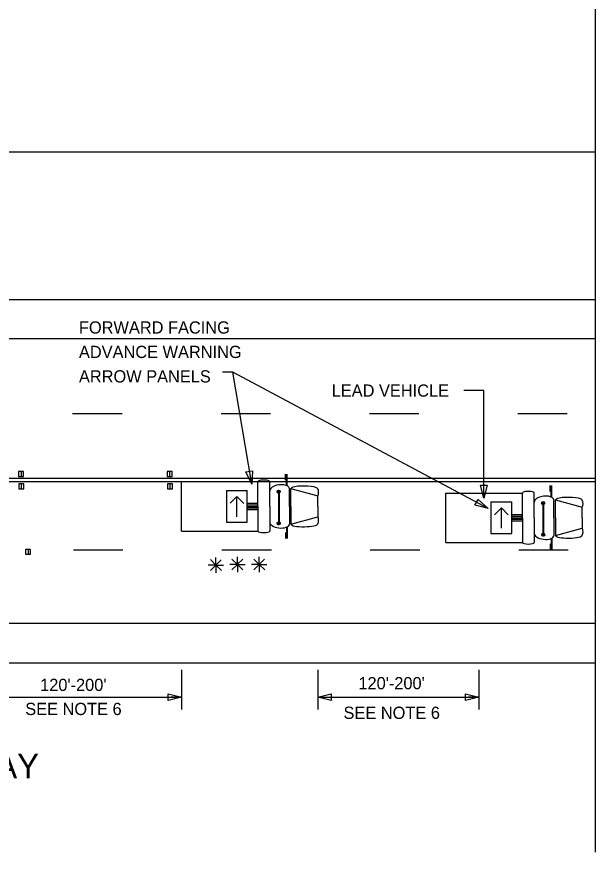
# Model space of a CAD drawing. Extents: x -747 to 834, y -5485 to -3577.
# Drawn here: x -230.7 to 53, y -5484.5 to -5074.5 of the extents above; entities that cross this region are included whole.
import ezdxf

# ---------------------------------------------------------------- set-up
doc = ezdxf.new("R2010")
doc.units = 0
doc.layers.add('Working Level 1', color=7, linetype='Continuous')

msp = doc.modelspace()

# ---------------------------------------------------------------- linework, layer by layer
at = {"layer": 'Working Level 1'}
for p, q in [((52.99, -4442.19), (52.99, -5484.51)), ((-746.8, -5140.74), (52.65, -5140.74)), ((-470.08, -5213.17), (52.99, -5213.17)), ((-475.5, -5232.41), (52.99, -5232.41)), ((0.51, -5315.84), (-124.65, -5248.83)), ((-229.72, -5297.59), (-229.73, -5300.02)), ((-227.3, -5297.59), (-229.72, -5297.59)), ((-228.51, -5297.59), (-228.51, -5300.02)), ((-227.3, -5300.02), (-227.3, -5297.59)), ((-154.46, -5297.59), (-156.89, -5297.59)), ((-156.89, -5297.59), (-156.89, -5300.02)), ((-155.67, -5297.59), (-155.67, -5300.02)), ((-154.46, -5300.02), (-154.46, -5297.59)), ((-474.52, -5300.89), (52.99, -5300.89)), ((-229.73, -5300.02), (-227.3, -5300.02)), ((-156.89, -5300.02), (-154.46, -5300.02)), ((-98.87, -5301.9), (-98.87, -5298.94)), ((-98.4, -5304.76), (-98.4, -5298.94)), ((-98, -5304.76), (-98, -5298.94)), ((-59.65, -5300.89), (52.99, -5300.89)), ((-474.18, -5302.58), (52.99, -5302.58)), ((-227.19, -5303.76), (-229.62, -5303.76)), ((-229.62, -5303.76), (-229.62, -5306.19)), ((-228.4, -5303.76), (-228.4, -5306.19)), ((-227.19, -5306.19), (-227.19, -5303.76)), ((-154.35, -5303.76), (-156.78, -5303.76)), ((-156.78, -5303.76), (-156.78, -5306.19)), ((-155.56, -5303.76), (-155.57, -5306.19)), ((-154.35, -5306.19), (-154.35, -5303.76)), ((-149.92, -5302.63), (-112.38, -5302.63)), ((-149.92, -5326.89), (-149.92, -5302.63)), ((-112.38, -5314.76), (-112.38, -5302.63)), ((-106.63, -5314.76), (-106.63, -5302.63)), ((30.82, -5307.48), (30.82, -5304.51)), ((31.29, -5310.34), (31.29, -5304.51)), ((31.69, -5310.34), (31.69, -5304.51)), ((-229.62, -5306.19), (-227.19, -5306.19)), ((-156.78, -5306.19), (-154.35, -5306.19)), ((-127.87, -5306.99), (-117.61, -5306.99)), ((-127.87, -5306.99), (-127.87, -5322.52)), ((-122.74, -5309.96), (-126.03, -5313.25)), ((-122.74, -5319.89), (-122.74, -5309.96)), ((-122.74, -5309.96), (-119.36, -5313.33)), ((-117.61, -5322.52), (-117.61, -5306.99)), ((-102.96, -5307.38), (-102.96, -5307.38)), ((-102.34, -5307.73), (-102.34, -5322.79)), ((-102.3, -5307.73), (-102.3, -5322.79)), ((-102.26, -5307.73), (-102.26, -5322.79)), ((-102.18, -5307.73), (-102.18, -5322.79)), ((-102.08, -5306.88), (-102.08, -5306.88)), ((-102.06, -5307.73), (-102.06, -5322.79)), ((-96.99, -5314.76), (-96.99, -5306.02)), ((-96.19, -5306.02), (-83.06, -5309.61)), ((-96.19, -5314.76), (-96.19, -5306.02)), ((-83.06, -5314.76), (-83.06, -5309.61)), ((-20.23, -5308.21), (17.31, -5308.21)), ((-20.23, -5332.46), (-20.23, -5308.21)), ((17.31, -5320.33), (17.31, -5308.21)), ((23.06, -5320.33), (23.06, -5308.21)), ((-117.61, -5313.21), (-112.38, -5313.21)), ((-117.61, -5313.98), (-112.38, -5313.98)), ((1.82, -5312.57), (12.08, -5312.57)), ((1.82, -5312.57), (1.82, -5328.09)), ((12.08, -5328.09), (12.08, -5312.57)), ((26.73, -5312.96), (26.73, -5312.96)), ((27.35, -5313.31), (27.35, -5328.36)), ((27.39, -5313.31), (27.39, -5328.36)), ((27.43, -5313.31), (27.43, -5328.36)), ((27.51, -5313.31), (27.51, -5328.36)), ((27.61, -5312.45), (27.61, -5312.45)), ((27.63, -5313.31), (27.63, -5328.36)), ((32.7, -5320.33), (32.7, -5311.6)), ((33.5, -5311.6), (46.63, -5315.19)), ((33.5, -5320.33), (33.5, -5311.6)), ((-117.61, -5314.76), (-112.38, -5314.76)), ((-117.61, -5315.53), (-112.38, -5315.53)), ((-117.61, -5316.31), (-112.38, -5316.31)), ((-112.38, -5314.76), (-112.38, -5326.88)), ((-106.63, -5314.76), (-106.63, -5326.88)), ((-96.99, -5314.76), (-96.99, -5323.49)), ((-96.19, -5314.76), (-96.19, -5323.49)), ((-83.06, -5314.76), (-83.06, -5319.9)), ((6.95, -5315.53), (3.66, -5318.83)), ((6.95, -5325.46), (6.95, -5315.53)), ((6.95, -5315.53), (10.33, -5318.91)), ((46.63, -5320.33), (46.63, -5315.19)), ((-96.19, -5323.49), (-83.06, -5319.9)), ((12.08, -5318.78), (17.31, -5318.78)), ((12.08, -5319.56), (17.31, -5319.56)), ((12.08, -5320.33), (17.31, -5320.33)), ((12.08, -5321.11), (17.31, -5321.11)), ((12.08, -5321.88), (17.31, -5321.88)), ((17.31, -5320.33), (17.31, -5332.46)), ((23.06, -5320.33), (23.06, -5332.46)), ((32.7, -5320.33), (32.7, -5329.07)), ((33.5, -5320.33), (33.5, -5329.07)), ((46.63, -5320.33), (46.63, -5325.48)), ((-127.87, -5322.52), (-117.61, -5322.52)), ((-102.92, -5322.92), (-102.92, -5322.92)), ((-102.04, -5322.41), (-102.04, -5322.41)), ((-98.4, -5324.75), (-98.4, -5330.58)), ((-98, -5324.75), (-98, -5330.58)), ((33.5, -5329.07), (46.63, -5325.48)), ((-149.92, -5326.88), (-112.38, -5326.88)), ((-98.87, -5327.61), (-98.87, -5330.58)), ((1.82, -5328.09), (12.08, -5328.09)), ((26.77, -5328.49), (26.77, -5328.49)), ((27.65, -5327.98), (27.65, -5327.98)), ((31.29, -5330.33), (31.29, -5336.15)), ((31.69, -5330.33), (31.69, -5336.15)), ((-20.23, -5332.46), (17.31, -5332.46)), ((30.82, -5333.18), (30.82, -5336.15)), ((-223.87, -5335.86), (-226.3, -5335.86)), ((-226.3, -5335.86), (-226.3, -5338.29)), ((-226.3, -5338.29), (-223.87, -5338.29)), ((-225.08, -5335.86), (-225.09, -5338.29)), ((-223.87, -5338.29), (-223.87, -5335.86)), ((-132.97, -5343.55), (-135.63, -5340.89)), ((-133.03, -5343.6), (-130.37, -5340.94)), ((-132.97, -5343.55), (-132.97, -5339.78)), ((-122.46, -5343.31), (-125.12, -5340.65)), ((-122.53, -5343.36), (-119.86, -5340.7)), ((-122.46, -5343.31), (-122.46, -5339.54)), ((-111.72, -5343.31), (-114.38, -5340.65)), ((-111.79, -5343.36), (-109.12, -5340.7)), ((-111.72, -5343.31), (-111.72, -5339.54)), ((-132.97, -5343.55), (-136.73, -5343.55)), ((-132.97, -5343.55), (-135.63, -5346.21)), ((-132.97, -5343.55), (-130.31, -5346.21)), ((-132.97, -5343.55), (-132.97, -5347.31)), ((-132.97, -5343.55), (-129.21, -5343.55)), ((-122.46, -5343.31), (-126.23, -5343.31)), ((-122.46, -5343.31), (-125.12, -5345.97)), ((-122.46, -5343.31), (-119.8, -5345.97)), ((-122.46, -5343.31), (-122.46, -5347.07)), ((-122.46, -5343.31), (-118.7, -5343.31)), ((-111.72, -5343.31), (-115.49, -5343.31)), ((-111.72, -5343.31), (-114.38, -5345.97)), ((-111.72, -5343.31), (-109.06, -5345.97)), ((-111.72, -5343.31), (-111.72, -5347.07)), ((-111.72, -5343.31), (-107.96, -5343.31)), ((-747.06, -5372.07), (52.99, -5372.07)), ((-747.06, -5391.46), (52.99, -5391.46)), ((-149.89, -5394.93), (-149.89, -5414.4)), ((-83.02, -5394.93), (-83.02, -5414.4)), ((-4.13, -5394.93), (-4.13, -5414.4)), ((-249.33, -5408.34), (-149.89, -5408.34)), ((-83.02, -5408.34), (-77.51, -5408.34)), ((-83.02, -5408.34), (-4.13, -5408.34))]:
    msp.add_line(p, q, dxfattribs=at)
for points in [[(-115.37, -5303.94), (-124.65, -5248.83), (-129.84, -5248.83)], [(-1.62, -5310.8), (-1.62, -5257.93), (-11.42, -5257.93)], [(-203.24, -5269.15), (-178.99, -5269.15)], [(-130.49, -5269.15), (-106.23, -5269.15)], [(-57.73, -5269.15), (-33.48, -5269.15)], [(15.02, -5269.15), (39.28, -5269.15)], [(-102.98, -5307.65), (-102.72, -5308.1)], [(-102.96, -5307.38), (-102.48, -5308.23)], [(-102.9, -5307.2), (-102.29, -5308.27)], [(-102.81, -5307.07), (-102.13, -5308.25)], [(-102.7, -5306.97), (-101.98, -5308.21)], [(-102.58, -5306.88), (-101.86, -5308.14)], [(-102.44, -5306.84), (-101.75, -5308.04)], [(-102.29, -5306.81), (-101.65, -5307.92)], [(-102.1, -5306.83), (-101.58, -5307.75)], [(-101.89, -5306.91), (-101.54, -5307.52)], [(26.71, -5313.22), (26.97, -5313.68)], [(26.73, -5312.96), (27.21, -5313.81)], [(26.79, -5312.78), (27.4, -5313.84)], [(26.88, -5312.64), (27.56, -5313.83)], [(26.99, -5312.54), (27.71, -5313.78)], [(27.11, -5312.46), (27.83, -5313.72)], [(27.25, -5312.42), (27.94, -5313.62)], [(27.4, -5312.38), (28.04, -5313.49)], [(27.59, -5312.41), (28.11, -5313.33)], [(27.8, -5312.49), (28.15, -5313.1)], [(-102.94, -5323.18), (-102.67, -5323.64)], [(-102.92, -5322.92), (-102.43, -5323.76)], [(-102.86, -5322.73), (-102.25, -5323.8)], [(-102.77, -5322.6), (-102.09, -5323.78)], [(-102.66, -5322.5), (-101.94, -5323.74)], [(-102.54, -5322.42), (-101.81, -5323.67)], [(-102.4, -5322.38), (-101.7, -5323.58)], [(-102.25, -5322.34), (-101.61, -5323.45)], [(-102.06, -5322.36), (-101.53, -5323.29)], [(-101.85, -5322.44), (-101.5, -5323.06)], [(26.75, -5328.75), (27.02, -5329.21)], [(26.77, -5328.49), (27.26, -5329.34)], [(26.83, -5328.31), (27.44, -5329.37)], [(26.92, -5328.17), (27.6, -5329.36)], [(27.03, -5328.07), (27.75, -5329.31)], [(27.15, -5327.99), (27.88, -5329.25)], [(27.29, -5327.95), (27.99, -5329.15)], [(27.44, -5327.92), (28.08, -5329.02)], [(27.63, -5327.94), (28.16, -5328.86)], [(27.84, -5328.02), (28.19, -5328.63)], [(-202.81, -5336.14), (-178.55, -5336.14)], [(-130.05, -5336.14), (-105.8, -5336.14)], [(-57.3, -5336.14), (-33.04, -5336.14)], [(15.46, -5336.14), (39.71, -5336.14)], [(-149.89, -5408.34), (-154.91, -5408.34), (-154.91, -5408.69)], [(-4.13, -5408.34), (-9.15, -5408.34), (-9.15, -5408.69)]]:
    msp.add_lwpolyline(points, dxfattribs=at)
for points in [[(-115.06, -5297.25), (-115.37, -5303.94), (-118.25, -5297.89)], [(0, -5304.3), (-1.62, -5310.8), (-3.25, -5304.3)], [(-4.45, -5311.34), (0.51, -5315.84), (-5.98, -5314.2)], [(-156.39, -5406.71), (-149.89, -5408.34), (-156.39, -5409.96)], [(-76.52, -5409.96), (-83.02, -5408.34), (-76.52, -5406.71)], [(-10.63, -5406.71), (-4.13, -5408.34), (-10.63, -5409.96)]]:
    msp.add_lwpolyline(points, close=True, dxfattribs=at)
for centre in [(-102.26, -5307.54), (27.43, -5313.11), (-102.22, -5323.07), (27.47, -5328.65)]:
    msp.add_circle(centre, 0.728, dxfattribs=at)
for centre in [(-86.27, -5307.9), (43.42, -5313.47), (-86.27, -5321.62), (43.42, -5327.2)]:
    msp.add_arc(centre, 3.64, 331.8801, 28.1199, dxfattribs=at)
for centre, major_axis, ratio, start_param, end_param in [((-109.5, -5302.63), (2.88, 0), 0.269913, 0, 3.141593), ((-101.81, -5306.62), (4.82, 0.6), 0.503092, 0, 3.141593), ((-89.62, -5306.1), (6.56, -0.08), 0.2034, 0, 3.141593), ((20.19, -5308.21), (2.88, 0), 0.269913, 0, 3.141593), ((27.88, -5312.2), (4.82, 0.6), 0.503092, 0, 3.141593), ((40.07, -5311.67), (6.56, -0.08), 0.2034, 0, 3.141593), ((-101.81, -5322.9), (4.82, -0.6), 0.503092, 3.141593, 6.283185), ((-89.62, -5323.42), (6.56, 0.08), 0.2034, 3.141593, 6.283185), ((-109.5, -5326.88), (2.88, 0), 0.269913, 3.141593, 6.283185), ((27.88, -5328.47), (4.82, -0.6), 0.503092, 3.141593, 6.283185), ((40.07, -5328.99), (6.56, 0.08), 0.2034, 3.141593, 6.283185), ((20.19, -5332.46), (2.88, 0), 0.269913, 3.141593, 6.283185)]:
    msp.add_ellipse(centre, major_axis=major_axis, ratio=ratio, start_param=start_param, end_param=end_param, dxfattribs=at)

# ---------------------------------------------------------------- texts
for s, p in [('FORWARD FACING', (-200.15, -5229.96)), ('ADVANCE WARNING ', (-200.15, -5241.96)), ('ARROW PANELS', (-200.15, -5253.96)), ('LEAD VEHICLE', (-76.23, -5260.93)), ("120'-200'", (-219.17, -5405.35)), ("120'-200'", (-63.13, -5404.51)), ('SEE NOTE 6', (-226.47, -5417.16)), ('SEE NOTE 6', (-70.43, -5419.04))]:
    msp.add_text(s, height=6, dxfattribs=at).set_placement(p)
msp.add_text('UNDIVIDED MULTILANE HIGHWAY', height=12, rotation=0, dxfattribs=at).set_placement((-483.65, -5448.15))

doc.saveas('drawing.dxf')
